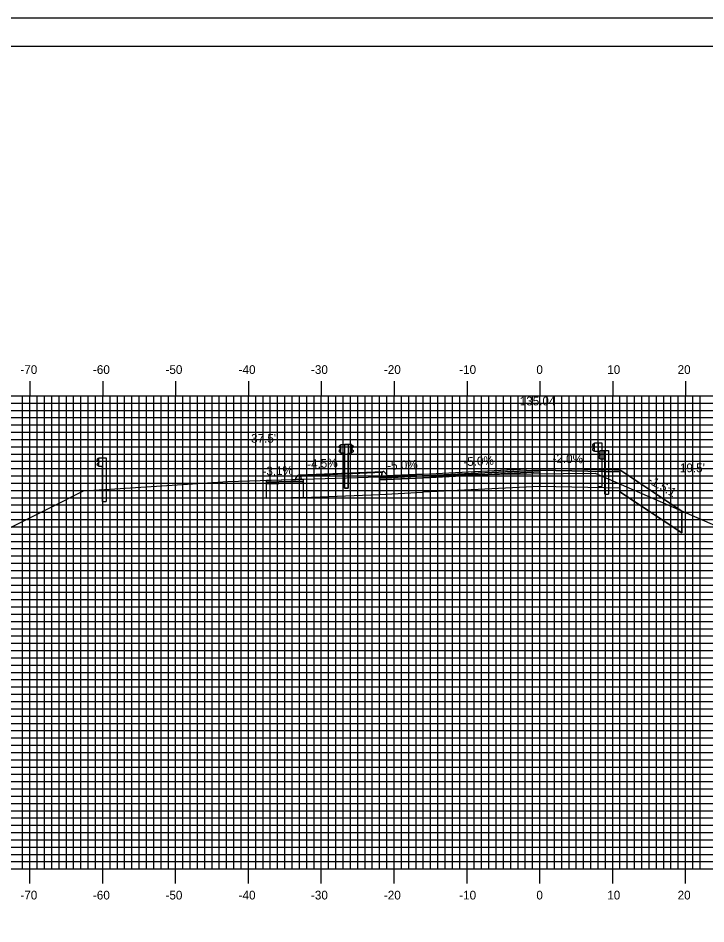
# Model space of a CAD drawing. Extents: x 859471 to 859814, y 364765 to 364985.
# Drawn here: x 859565.3 to 859659.7, y 364860.7 to 364985.2 of the extents above; entities that cross this region are included whole.
import ezdxf

# ---------------------------------------------------------------- set-up
doc = ezdxf.new("R2010")
doc.units = 0
for name, color, linetype in [('ANNOTATION', 7, 'Continuous'), ('BORDER', 7, 'Continuous'), ('D_Curb_Type_3M2_Lt', 7, 'Continuous'), ('D_Curb_Type_3M2_Rt', 7, 'Continuous'), ('D_Guardrail_Beam_Rt', 7, 'Continuous'), ('D_Roadway_Centerline', 7, 'Continuous'), ('D_Roadway_Centerline_Text', 7, 'Continuous'), ('D_Roadway_Edge_Shoulder', 7, 'Continuous'), ('D_Roadway_Edge_TW', 7, 'Continuous'), ('D_Roadway_FinishedGrade', 7, 'Continuous'), ('D_Roadway_Pavement', 7, 'Continuous'), ('D_Roadway_SubGrade', 7, 'Continuous'), ('D_Text_Standard', 7, 'Continuous'), ('H_V ANNOTATION', 7, 'Continuous'), ('M_Guardrail', 7, 'Continuous'), ('M_Roadway_Centerline', 7, 'Continuous'), ('MAJOR', 7, 'Continuous'), ('MINOR', 7, 'Continuous'), ('PATTERNING', 7, 'Continuous'), ('PLOT BOUNDARY', 7, 'Continuous'), ('S_Roadway_Centerline', 7, 'Continuous')]:
    doc.layers.add(name, color=color, linetype=linetype)

msp = doc.modelspace()

# ---------------------------------------------------------------- linework, layer by layer
at = {"layer": 'BORDER'}
msp.add_lwpolyline([(859487.27, 364771.3), (859807.27, 364771.3), (859807.27, 364981.3), (859487.27, 364981.3)], close=True, dxfattribs=at)
at = {"layer": 'D_Curb_Type_3M2_Lt'}
for p, q in [((859615.23, 364922.79), (859615.12, 364922.29)), ((859615.37, 364922.92), (859615.37, 364922.92)), ((859615.87, 364922.46), (859615.52, 364922.86)), ((859615.87, 364922.29), (859615.87, 364922.46)), ((859615.12, 364922.29), (859615.87, 364922.29))]:
    msp.add_line(p, q, dxfattribs=at)
msp.add_arc((859615.39, 364922.75), 0.167, 41.387, 167.6648, dxfattribs=at)
at = {"layer": 'D_Curb_Type_3M2_Rt'}
for p, q in [((859603.36, 364921.98), (859603.71, 364922.38)), ((859603.36, 364921.81), (859603.36, 364921.98)), ((859604.11, 364921.81), (859603.36, 364921.81)), ((859604, 364922.3), (859604.11, 364921.81))]:
    msp.add_line(p, q, dxfattribs=at)
msp.add_arc((859603.84, 364922.27), 0.167, 12.3352, 138.613, dxfattribs=at)
at = {"layer": 'D_Guardrail_Beam_Rt'}
for p, q in [((859645.05, 364925.66), (859644.91, 364925.56)), ((859644.91, 364925.42), (859645.11, 364925.28)), ((859645.11, 364925.08), (859644.91, 364924.95)), ((859645.14, 364925.68), (859645.07, 364925.67)), ((859645.14, 364925.77), (859645.83, 364925.77)), ((859645.14, 364924.6), (859645.14, 364925.77)), ((859645.14, 364925.22), (859645.14, 364925.15)), ((859645.66, 364925.77), (859645.66, 364924.6)), ((859645.77, 364925.77), (859645.77, 364924.6)), ((859645.83, 364925.77), (859646.3, 364925.77)), ((859645.83, 364925.77), (859645.83, 364924.6)), ((859646.3, 364925.77), (859646.3, 364919.77)), ((859644.91, 364924.8), (859645.05, 364924.7)), ((859645.07, 364924.7), (859645.14, 364924.68)), ((859645.83, 364924.6), (859645.14, 364924.6)), ((859645.81, 364919.77), (859645.81, 364924.6)), ((859645.81, 364919.77), (859646.3, 364919.77))]:
    msp.add_line(p, q, dxfattribs=at)
for centre, major_axis, start_param, end_param in [((859644.96, 364925.49), (-0.0877, 0), 5.323254, 7.243116), ((859644.96, 364924.88), (-0.0877, 0), 5.323254, 7.243116), ((859645.08, 364925.63), (-0.0417, 0), 4.907132, 5.323254), ((859645.06, 364925.22), (0.0789, 0), 0, 0.959931), ((859645.06, 364925.15), (0.0789, 0), 5.323254, 6.283185), ((859645.08, 364924.74), (-0.0417, 0), 0.959931, 1.376053)]:
    msp.add_ellipse(centre, major_axis=major_axis, ratio=0.995501, start_param=start_param, end_param=end_param, dxfattribs=at)
at = {"layer": 'D_Roadway_Centerline'}
for points in [[(859615.87, 364922.29), (859618.23, 364922.41), (859620.87, 364922.54), (859620.87, 364922.54), (859636.78, 364923.34), (859636.87, 364923.34), (859636.93, 364923.34), (859644.87, 364923.18), (859644.87, 364923.18), (859647.07, 364923.14), (859647.87, 364923.12), (859656.37, 364917.46)], [(859599.36, 364921.69), (859603.36, 364921.81), (859603.36, 364921.81)]]:
    msp.add_lwpolyline(points, dxfattribs=at)
at = {"layer": 'D_Roadway_Edge_Shoulder'}
for points in [[(859620.87, 364922.54), (859615.87, 364922.29), (859614.87, 364922.24), (859614.87, 364921.99), (859620.87, 364922.29)], [(859636.87, 364923.34), (859644.87, 364923.18), (859644.87, 364923.18), (859647.87, 364923.12), (859647.87, 364922.87), (859636.87, 364923.09)], [(859599.36, 364921.69), (859603.36, 364921.81), (859604.36, 364921.84), (859604.36, 364921.59), (859599.36, 364921.44)]]:
    msp.add_lwpolyline(points, close=True, dxfattribs=at)
at = {"layer": 'D_Roadway_Edge_TW'}
msp.add_lwpolyline([(859620.87, 364922.54), (859636.87, 364923.34), (859636.87, 364923.09), (859620.87, 364922.29)], close=True, dxfattribs=at)
at = {"layer": 'D_Roadway_FinishedGrade'}
msp.add_line((859647.87, 364923.12), (859647.87, 364920.12), dxfattribs=at)
for points in [[(859603.88, 364922.43), (859615.35, 364922.91)], [(859647.87, 364923.12), (859649.37, 364922.12), (859656.37, 364917.46)], [(859656.37, 364917.46), (859656.37, 364914.46), (859647.87, 364920.12)]]:
    msp.add_lwpolyline(points, dxfattribs=at)
at = {"layer": 'D_Roadway_Pavement'}
for points in [[(859620.87, 364922.29), (859636.87, 364923.09), (859636.87, 364922.84), (859620.87, 364922.04)], [(859599.36, 364921.44), (859604.36, 364921.59), (859604.36, 364921.34), (859599.36, 364921.19)], [(859620.87, 364922.29), (859614.87, 364921.99), (859614.87, 364921.74), (859620.87, 364922.04)]]:
    msp.add_lwpolyline(points, close=True, dxfattribs=at)
msp.add_lwpolyline([(859636.87, 364923.09), (859636.87, 364922.84)], dxfattribs=at)
msp.add_lwpolyline([(859636.87, 364923.09), (859636.87, 364922.84)], dxfattribs=at)
at = {"layer": 'D_Roadway_SubGrade'}
for points in [[(859604.36, 364921.84), (859604.36, 364919.34), (859614.87, 364919.74), (859614.87, 364921.74), (859614.87, 364921.99), (859614.87, 364922.24), (859615.12, 364922.26), (859615.22, 364922.74), (859604.01, 364922.27), (859604.11, 364921.83)], [(859620.87, 364922.04), (859636.87, 364922.84), (859636.87, 364920.84), (859620.87, 364920.04)], [(859636.87, 364922.84), (859636.87, 364923.09), (859647.87, 364922.87), (859647.87, 364923.12), (859647.87, 364920.62), (859636.87, 364920.84)], [(859599.36, 364921.19), (859604.36, 364921.34), (859604.36, 364921.59), (859604.36, 364919.34), (859599.36, 364919.19)], [(859620.87, 364922.04), (859614.87, 364921.74), (859614.87, 364921.99), (859614.87, 364919.74), (859620.87, 364920.04)]]:
    msp.add_lwpolyline(points, close=True, dxfattribs=at)
at = {"layer": 'M_Guardrail'}
for p, q in [((859609.47, 364926.5), (859609.33, 364926.4)), ((859609.33, 364926.26), (859609.52, 364926.12)), ((859609.57, 364926.52), (859609.49, 364926.51)), ((859609.57, 364926.6), (859610.06, 364926.6)), ((859609.57, 364925.43), (859609.57, 364926.6)), ((859610.04, 364926.6), (859610.04, 364920.6)), ((859610.54, 364926.6), (859610.04, 364926.6)), ((859610.06, 364926.6), (859610.55, 364926.6)), ((859610.06, 364926.6), (859610.06, 364925.43)), ((859611.03, 364926.6), (859610.54, 364926.6)), ((859610.54, 364926.6), (859610.54, 364925.43)), ((859610.55, 364926.6), (859610.55, 364920.6)), ((859611.03, 364925.43), (859611.03, 364926.6)), ((859611.03, 364926.52), (859611.11, 364926.51)), ((859611.27, 364926.26), (859611.07, 364926.12)), ((859611.12, 364926.5), (859611.27, 364926.4)), ((859644.28, 364926.73), (859644.14, 364926.63)), ((859644.14, 364926.48), (859644.33, 364926.35)), ((859644.33, 364926.13), (859644.14, 364925.99)), ((859644.38, 364926.75), (859644.3, 364926.73)), ((859644.37, 364926.28), (859644.37, 364926.19)), ((859644.38, 364926.82), (859644.87, 364926.82)), ((859644.38, 364925.65), (859644.38, 364926.82)), ((859644.87, 364926.82), (859645.36, 364926.82)), ((859644.87, 364926.82), (859644.87, 364925.65)), ((859645.36, 364926.82), (859645.36, 364920.82)), ((859609.52, 364925.9), (859609.33, 364925.77)), ((859609.33, 364925.63), (859609.47, 364925.53)), ((859609.49, 364925.52), (859609.57, 364925.5)), ((859609.55, 364926.06), (859609.55, 364925.97)), ((859610.06, 364925.43), (859609.57, 364925.43)), ((859610.06, 364920.6), (859610.06, 364925.43)), ((859610.54, 364920.6), (859610.54, 364925.43)), ((859610.54, 364925.43), (859611.03, 364925.43)), ((859611.11, 364925.52), (859611.03, 364925.5)), ((859611.04, 364926.06), (859611.04, 364925.97)), ((859611.07, 364925.9), (859611.27, 364925.77)), ((859611.27, 364925.63), (859611.12, 364925.53)), ((859644.14, 364925.85), (859644.28, 364925.75)), ((859644.3, 364925.74), (859644.38, 364925.73)), ((859644.87, 364925.65), (859644.38, 364925.65)), ((859644.87, 364920.82), (859644.87, 364925.65)), ((859576.25, 364924.67), (859576.11, 364924.57)), ((859576.11, 364924.43), (859576.31, 364924.29)), ((859576.31, 364924.07), (859576.11, 364923.94)), ((859576.11, 364923.8), (859576.25, 364923.7)), ((859576.35, 364924.69), (859576.27, 364924.68)), ((859576.27, 364923.69), (859576.35, 364923.67)), ((859576.34, 364924.23), (859576.34, 364924.14)), ((859576.35, 364924.77), (859576.84, 364924.77)), ((859576.35, 364923.6), (859576.35, 364924.77)), ((859576.84, 364923.6), (859576.35, 364923.6)), ((859576.84, 364924.77), (859577.33, 364924.77)), ((859576.84, 364924.77), (859576.84, 364923.6)), ((859576.84, 364918.77), (859576.84, 364923.6)), ((859577.33, 364924.77), (859577.33, 364918.77)), ((859610.54, 364920.6), (859610.04, 364920.6)), ((859610.06, 364920.6), (859610.55, 364920.6)), ((859644.87, 364920.82), (859645.36, 364920.82)), ((859576.84, 364918.77), (859577.33, 364918.77))]:
    msp.add_line(p, q, dxfattribs=at)
for centre, major_axis, start_param, end_param in [((859609.38, 364926.33), (-0.0877, 0), 5.323254, 7.243116), ((859609.49, 364926.47), (-0.0417, 0), 4.886922, 5.323254), ((859609.48, 364926.06), (0.0789, 0), 0, 0.959931), ((859611.12, 364926.06), (-0.0789, 0), 5.323254, 6.283185), ((859611.1, 364926.47), (0.0417, 0), 0.959931, 1.396263), ((859611.22, 364926.33), (0.0877, 0), 5.323254, 7.243116), ((859644.19, 364926.55), (-0.0877, 0), 5.323254, 7.243116), ((859644.31, 364926.69), (-0.0417, 0), 4.886922, 5.323254), ((859644.29, 364926.28), (0.0789, 0), 0, 0.959931), ((859644.29, 364926.19), (0.0789, 0), 5.323254, 6.283185), ((859609.38, 364925.7), (-0.0877, 0), 5.323254, 7.243116), ((859609.49, 364925.56), (-0.0417, 0), 0.959931, 1.396263), ((859609.48, 364925.97), (0.0789, 0), 5.323254, 6.283185), ((859611.12, 364925.97), (-0.0789, 0), 6.283185, 7.243116), ((859611.1, 364925.56), (0.0417, 0), 4.886922, 5.323254), ((859611.22, 364925.7), (0.0877, 0), 5.323254, 7.243116), ((859644.19, 364925.92), (-0.0877, 0), 5.323254, 7.243116), ((859644.31, 364925.78), (-0.0417, 0), 0.959931, 1.396263), ((859576.16, 364924.5), (-0.0877, 0), 5.323254, 7.243116), ((859576.16, 364923.87), (-0.0877, 0), 5.323254, 7.243116), ((859576.28, 364924.64), (-0.0417, 0), 4.886922, 5.323254), ((859576.28, 364923.73), (-0.0417, 0), 0.959931, 1.396263), ((859576.26, 364924.23), (0.0789, 0), 0, 0.959931), ((859576.26, 364924.14), (0.0789, 0), 5.323254, 6.283185)]:
    msp.add_ellipse(centre, major_axis=major_axis, ratio=0.995501, start_param=start_param, end_param=end_param, dxfattribs=at)
at = {"layer": 'MAJOR'}
for p, q in [((859566.87, 364935.31), (859566.87, 364933.3)), ((859576.87, 364935.31), (859576.87, 364933.3)), ((859586.87, 364935.31), (859586.87, 364933.3)), ((859596.87, 364935.31), (859596.87, 364933.3)), ((859606.87, 364935.31), (859606.87, 364933.3)), ((859616.87, 364935.31), (859616.87, 364933.3)), ((859626.87, 364935.31), (859626.87, 364933.3)), ((859636.87, 364935.31), (859636.87, 364933.3)), ((859646.87, 364935.31), (859646.87, 364933.3)), ((859656.87, 364935.31), (859656.87, 364933.3)), ((859496.87, 364933.3), (859776.87, 364933.3)), ((859496.87, 364933.3), (859776.87, 364933.3)), ((859566.87, 364868.3), (859566.87, 364933.3)), ((859576.87, 364868.3), (859576.87, 364933.3)), ((859586.87, 364868.3), (859586.87, 364933.3)), ((859596.87, 364868.3), (859596.87, 364933.3)), ((859606.87, 364868.3), (859606.87, 364933.3)), ((859616.87, 364868.3), (859616.87, 364933.3)), ((859626.87, 364868.3), (859626.87, 364933.3)), ((859636.87, 364868.3), (859636.87, 364933.3)), ((859646.87, 364868.3), (859646.87, 364933.3)), ((859656.87, 364868.3), (859656.87, 364933.3)), ((859496.87, 364928.3), (859776.87, 364928.3)), ((859496.87, 364923.3), (859776.87, 364923.3)), ((859496.87, 364918.3), (859776.87, 364918.3)), ((859496.87, 364913.3), (859776.87, 364913.3)), ((859496.87, 364908.3), (859776.87, 364908.3)), ((859496.87, 364903.3), (859776.87, 364903.3)), ((859496.87, 364898.3), (859776.87, 364898.3)), ((859496.87, 364893.3), (859776.87, 364893.3)), ((859496.87, 364888.3), (859776.87, 364888.3)), ((859496.87, 364883.3), (859776.87, 364883.3)), ((859496.87, 364878.3), (859776.87, 364878.3)), ((859496.87, 364873.3), (859776.87, 364873.3)), ((859496.87, 364868.3), (859776.87, 364868.3)), ((859496.87, 364868.3), (859776.87, 364868.3)), ((859566.87, 364866.3), (859566.87, 364868.3)), ((859576.87, 364866.3), (859576.87, 364868.3)), ((859586.87, 364866.3), (859586.87, 364868.3)), ((859596.87, 364866.3), (859596.87, 364868.3)), ((859606.87, 364866.3), (859606.87, 364868.3)), ((859616.87, 364866.3), (859616.87, 364868.3)), ((859626.87, 364866.3), (859626.87, 364868.3)), ((859636.87, 364866.3), (859636.87, 364868.3)), ((859646.87, 364866.3), (859646.87, 364868.3)), ((859656.87, 364866.3), (859656.87, 364868.3))]:
    msp.add_line(p, q, dxfattribs=at)
at = {"layer": 'MINOR'}
for p, q in [((859496.87, 364932.3), (859776.87, 364932.3)), ((859565.87, 364868.3), (859565.87, 364933.3)), ((859567.87, 364868.3), (859567.87, 364933.3)), ((859568.87, 364868.3), (859568.87, 364933.3)), ((859569.87, 364868.3), (859569.87, 364933.3)), ((859570.87, 364868.3), (859570.87, 364933.3)), ((859571.87, 364868.3), (859571.87, 364933.3)), ((859572.87, 364868.3), (859572.87, 364933.3)), ((859573.87, 364868.3), (859573.87, 364933.3)), ((859574.87, 364868.3), (859574.87, 364933.3)), ((859575.87, 364868.3), (859575.87, 364933.3)), ((859577.87, 364868.3), (859577.87, 364933.3)), ((859578.87, 364868.3), (859578.87, 364933.3)), ((859579.87, 364868.3), (859579.87, 364933.3)), ((859580.87, 364868.3), (859580.87, 364933.3)), ((859581.87, 364868.3), (859581.87, 364933.3)), ((859582.87, 364868.3), (859582.87, 364933.3)), ((859583.87, 364868.3), (859583.87, 364933.3)), ((859584.87, 364868.3), (859584.87, 364933.3)), ((859585.87, 364868.3), (859585.87, 364933.3)), ((859587.87, 364868.3), (859587.87, 364933.3)), ((859588.87, 364868.3), (859588.87, 364933.3)), ((859589.87, 364868.3), (859589.87, 364933.3)), ((859590.87, 364868.3), (859590.87, 364933.3)), ((859591.87, 364868.3), (859591.87, 364933.3)), ((859592.87, 364868.3), (859592.87, 364933.3)), ((859593.87, 364868.3), (859593.87, 364933.3)), ((859594.87, 364868.3), (859594.87, 364933.3)), ((859595.87, 364868.3), (859595.87, 364933.3)), ((859597.87, 364868.3), (859597.87, 364933.3)), ((859598.87, 364868.3), (859598.87, 364933.3)), ((859599.87, 364868.3), (859599.87, 364933.3)), ((859600.87, 364868.3), (859600.87, 364933.3)), ((859601.87, 364868.3), (859601.87, 364933.3)), ((859602.87, 364868.3), (859602.87, 364933.3)), ((859603.87, 364868.3), (859603.87, 364933.3)), ((859604.87, 364868.3), (859604.87, 364933.3)), ((859605.87, 364868.3), (859605.87, 364933.3)), ((859607.87, 364868.3), (859607.87, 364933.3)), ((859608.87, 364868.3), (859608.87, 364933.3)), ((859609.87, 364868.3), (859609.87, 364933.3)), ((859610.87, 364868.3), (859610.87, 364933.3)), ((859611.87, 364868.3), (859611.87, 364933.3)), ((859612.87, 364868.3), (859612.87, 364933.3)), ((859613.87, 364868.3), (859613.87, 364933.3)), ((859614.87, 364868.3), (859614.87, 364933.3)), ((859615.87, 364868.3), (859615.87, 364933.3)), ((859617.87, 364868.3), (859617.87, 364933.3)), ((859618.87, 364868.3), (859618.87, 364933.3)), ((859619.87, 364868.3), (859619.87, 364933.3)), ((859620.87, 364868.3), (859620.87, 364933.3)), ((859621.87, 364868.3), (859621.87, 364933.3)), ((859622.87, 364868.3), (859622.87, 364933.3)), ((859623.87, 364868.3), (859623.87, 364933.3)), ((859624.87, 364868.3), (859624.87, 364933.3)), ((859625.87, 364868.3), (859625.87, 364933.3)), ((859627.87, 364868.3), (859627.87, 364933.3)), ((859628.87, 364868.3), (859628.87, 364933.3)), ((859629.87, 364868.3), (859629.87, 364933.3)), ((859630.87, 364868.3), (859630.87, 364933.3)), ((859631.87, 364868.3), (859631.87, 364933.3)), ((859632.87, 364868.3), (859632.87, 364933.3)), ((859633.87, 364868.3), (859633.87, 364933.3)), ((859634.87, 364868.3), (859634.87, 364933.3)), ((859635.87, 364868.3), (859635.87, 364933.3)), ((859637.87, 364868.3), (859637.87, 364933.3)), ((859638.87, 364868.3), (859638.87, 364933.3)), ((859639.87, 364868.3), (859639.87, 364933.3)), ((859640.87, 364868.3), (859640.87, 364933.3)), ((859641.87, 364868.3), (859641.87, 364933.3)), ((859642.87, 364868.3), (859642.87, 364933.3)), ((859643.87, 364868.3), (859643.87, 364933.3)), ((859644.87, 364868.3), (859644.87, 364933.3)), ((859645.87, 364868.3), (859645.87, 364933.3)), ((859647.87, 364868.3), (859647.87, 364933.3)), ((859648.87, 364868.3), (859648.87, 364933.3)), ((859649.87, 364868.3), (859649.87, 364933.3)), ((859650.87, 364868.3), (859650.87, 364933.3)), ((859651.87, 364868.3), (859651.87, 364933.3)), ((859652.87, 364868.3), (859652.87, 364933.3)), ((859653.87, 364868.3), (859653.87, 364933.3)), ((859654.87, 364868.3), (859654.87, 364933.3)), ((859655.87, 364868.3), (859655.87, 364933.3)), ((859657.87, 364868.3), (859657.87, 364933.3)), ((859658.87, 364868.3), (859658.87, 364933.3)), ((859496.87, 364931.3), (859776.87, 364931.3)), ((859496.87, 364930.3), (859776.87, 364930.3)), ((859496.87, 364929.3), (859776.87, 364929.3)), ((859496.87, 364927.3), (859776.87, 364927.3)), ((859496.87, 364926.3), (859776.87, 364926.3)), ((859496.87, 364925.3), (859776.87, 364925.3)), ((859496.87, 364924.3), (859776.87, 364924.3)), ((859496.87, 364922.3), (859776.87, 364922.3)), ((859496.87, 364921.3), (859776.87, 364921.3)), ((859496.87, 364920.3), (859776.87, 364920.3)), ((859496.87, 364919.3), (859776.87, 364919.3)), ((859496.87, 364917.3), (859776.87, 364917.3)), ((859496.87, 364916.3), (859776.87, 364916.3)), ((859496.87, 364915.3), (859776.87, 364915.3)), ((859496.87, 364914.3), (859776.87, 364914.3)), ((859496.87, 364912.3), (859776.87, 364912.3)), ((859496.87, 364911.3), (859776.87, 364911.3)), ((859496.87, 364910.3), (859776.87, 364910.3)), ((859496.87, 364909.3), (859776.87, 364909.3)), ((859496.87, 364907.3), (859776.87, 364907.3)), ((859496.87, 364906.3), (859776.87, 364906.3)), ((859496.87, 364905.3), (859776.87, 364905.3)), ((859496.87, 364904.3), (859776.87, 364904.3)), ((859496.87, 364902.3), (859776.87, 364902.3)), ((859496.87, 364901.3), (859776.87, 364901.3)), ((859496.87, 364900.3), (859776.87, 364900.3)), ((859496.87, 364899.3), (859776.87, 364899.3)), ((859496.87, 364897.3), (859776.87, 364897.3)), ((859496.87, 364896.3), (859776.87, 364896.3)), ((859496.87, 364895.3), (859776.87, 364895.3)), ((859496.87, 364894.3), (859776.87, 364894.3)), ((859496.87, 364892.3), (859776.87, 364892.3)), ((859496.87, 364891.3), (859776.87, 364891.3)), ((859496.87, 364890.3), (859776.87, 364890.3)), ((859496.87, 364889.3), (859776.87, 364889.3)), ((859496.87, 364887.3), (859776.87, 364887.3)), ((859496.87, 364886.3), (859776.87, 364886.3)), ((859496.87, 364885.3), (859776.87, 364885.3)), ((859496.87, 364884.3), (859776.87, 364884.3)), ((859496.87, 364882.3), (859776.87, 364882.3)), ((859496.87, 364881.3), (859776.87, 364881.3)), ((859496.87, 364880.3), (859776.87, 364880.3)), ((859496.87, 364879.3), (859776.87, 364879.3)), ((859496.87, 364877.3), (859776.87, 364877.3)), ((859496.87, 364876.3), (859776.87, 364876.3)), ((859496.87, 364875.3), (859776.87, 364875.3)), ((859496.87, 364874.3), (859776.87, 364874.3)), ((859496.87, 364872.3), (859776.87, 364872.3)), ((859496.87, 364871.3), (859776.87, 364871.3)), ((859496.87, 364870.3), (859776.87, 364870.3)), ((859496.87, 364869.3), (859776.87, 364869.3))]:
    msp.add_line(p, q, dxfattribs=at)
at = {"layer": 'PATTERNING'}
for p, q in [((859649.37, 364922.12), (859647.87, 364923.12)), ((859656.37, 364917.46), (859649.37, 364922.12))]:
    msp.add_line(p, q, dxfattribs=at)
for points in [[(859647.87, 364923.12), (859647.87, 364920.62), (859647.87, 364920.12)], [(859647.87, 364920.12), (859656.37, 364914.46), (859656.37, 364917.46)]]:
    msp.add_lwpolyline(points, dxfattribs=at)
at = {"layer": 'PLOT BOUNDARY'}
msp.add_lwpolyline([(859471.09, 364765.18), (859811.09, 364765.18), (859811.09, 364985.18), (859471.09, 364985.18)], close=True, dxfattribs=at)
at = {"layer": 'S_Roadway_Centerline'}
msp.add_lwpolyline([(859496.87, 364895.67), (859502.75, 364895.48), (859507.25, 364895.43), (859522.77, 364896.52), (859533.73, 364900.64), (859539.17, 364903.01), (859542.98, 364904.71), (859550.76, 364908.5), (859569.5, 364917.87), (859574.24, 364920.22), (859586.41, 364921), (859594.04, 364921.52), (859623.68, 364922.44), (859624.88, 364922.48), (859625.49, 364922.49), (859626.93, 364922.5), (859644.46, 364922.65), (859661.25, 364915.33)], dxfattribs=at)

# ---------------------------------------------------------------- texts
at = {"layer": 'ANNOTATION'}
for s, rotation, p in [('-5.0%', 2.8624, (859626.39, 364923.62)), ('-2.0%', 358.8541, (859638.59, 364924.11)), ('-3.1%', 1.7679, (859598.81, 364922.34)), ('-4.5%', 2.5525, (859604.95, 364923.31)), ('-5.0%', 2.8626, (859615.94, 364923.1)), ('-1.5:1', 330.177, (859651.59, 364921.39))]:
    msp.add_text(s, height=1.2, rotation=rotation, dxfattribs=at).set_placement(p)
at = {"layer": 'D_Roadway_Centerline_Text'}
msp.add_text('135.04', height=1.2, dxfattribs=at).set_placement((859634.1, 364931.98))
at = {"layer": 'D_Text_Standard'}
for s, p in [("37.5'", (859597.23, 364926.85)), ("19.5'", (859656.09, 364922.8))]:
    msp.add_text(s, height=1.2, dxfattribs=at).set_placement(p)
at = {"layer": 'H_V ANNOTATION'}
for s, p in [('-70', (859565.56, 364936.3)), ('-60', (859575.52, 364936.3)), ('-50', (859585.48, 364936.3)), ('-40', (859595.52, 364936.3)), ('-30', (859605.45, 364936.3)), ('-20', (859615.46, 364936.3)), ('-10', (859625.8, 364936.3)), ('0', (859636.39, 364936.3)), ('10', (859646.12, 364936.3)), ('20', (859655.78, 364936.3)), ('-70', (859565.56, 364864.1)), ('-60', (859575.52, 364864.1)), ('-50', (859585.48, 364864.1)), ('-40', (859595.52, 364864.1)), ('-30', (859605.45, 364864.1)), ('-20', (859615.46, 364864.1)), ('-10', (859625.8, 364864.1)), ('0', (859636.39, 364864.1)), ('10', (859646.12, 364864.1)), ('20', (859655.78, 364864.1))]:
    msp.add_text(s, height=1.2, dxfattribs=at).set_placement(p)
at = {"layer": 'M_Roadway_Centerline'}
for s, p in [('C', (859624.87, 364922.48)), ('L', (859624.88, 364922.47)), ('C', (859594.04, 364921.52)), ('L', (859594.04, 364921.51))]:
    msp.add_text(s, height=0.0146, dxfattribs=at).set_placement(p)

doc.saveas('drawing.dxf')
